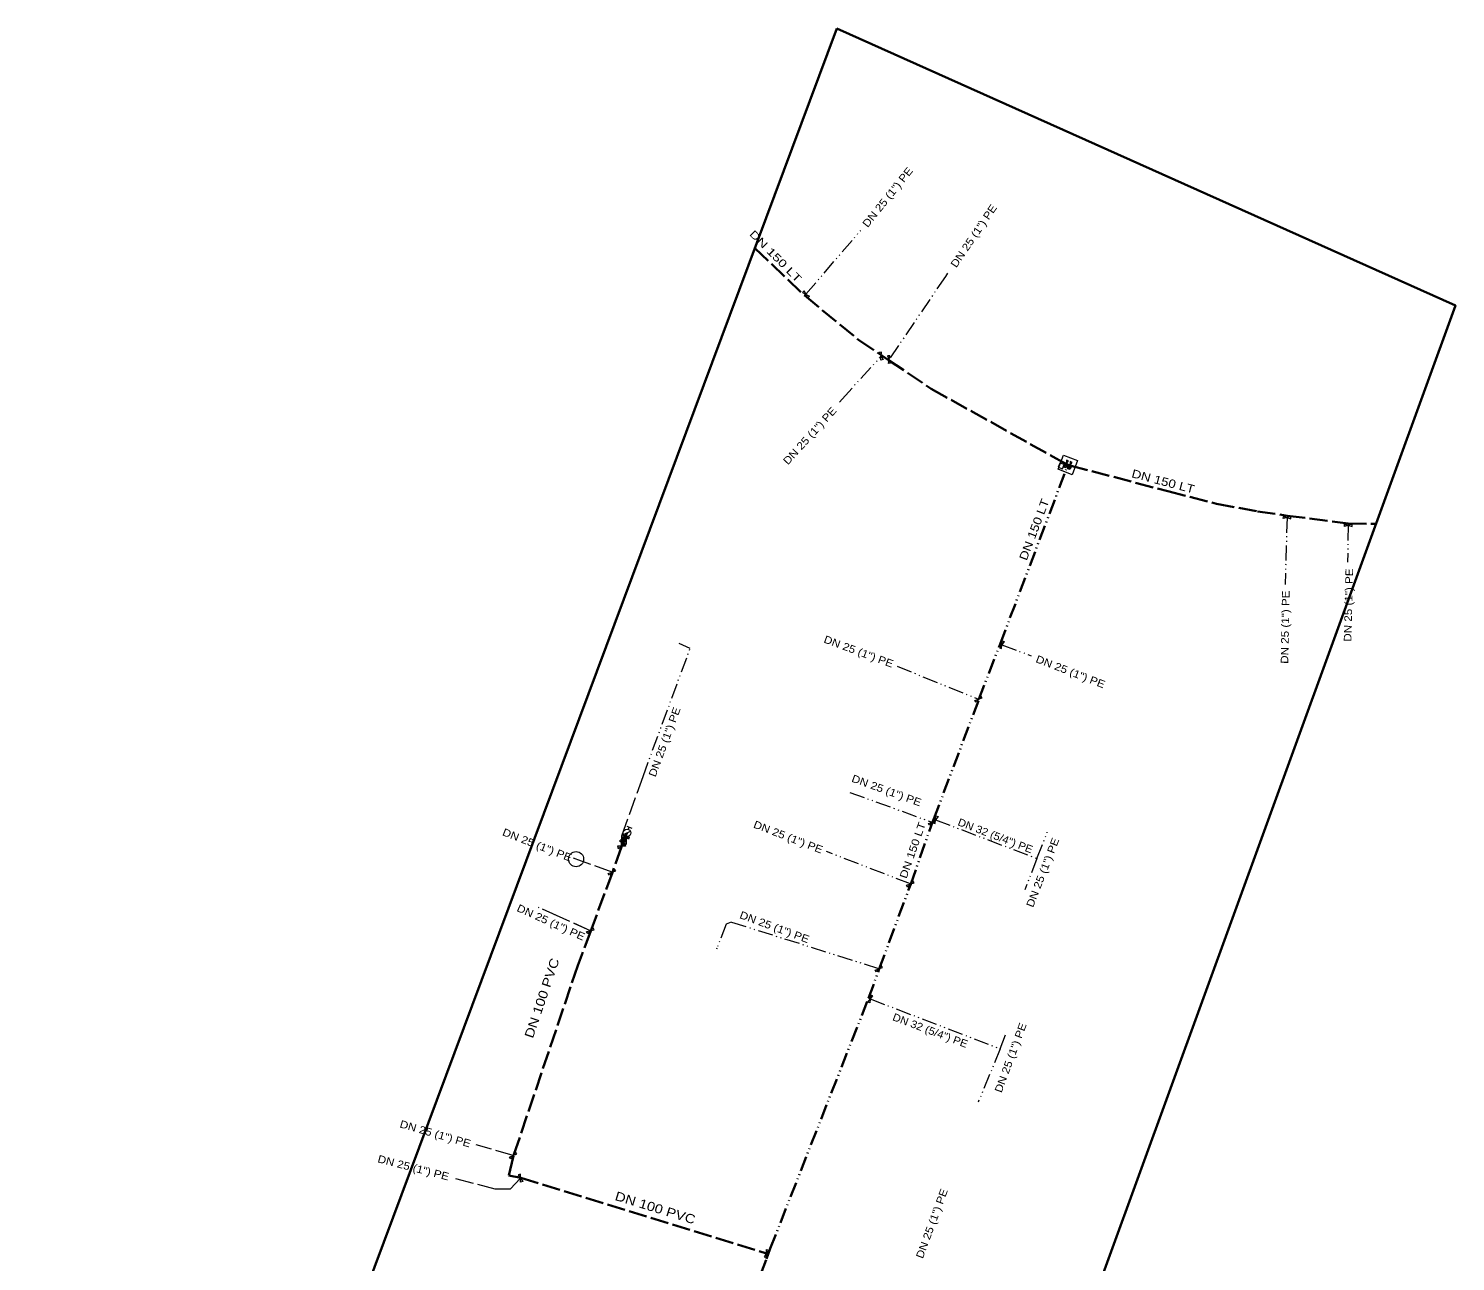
# Model space of a CAD drawing. Extents: x -644344 to -644155, y -1042441 to -1042139.
# Drawn here: x -644344 to -644155.2, y -1042301.7 to -1042138.6 of the extents above; entities that cross this region are included whole.
import ezdxf
from ezdxf.enums import TextEntityAlignment as Align

# ---------------------------------------------------------------- set-up
doc = ezdxf.new("R2010")
doc.units = 0
doc.header["$LTSCALE"] = 0.4
doc.linetypes.add('DASH_DOUBLE_DOT', pattern=[9.2, 5, -1.2, 0.3, -1.2, 0.3, -1.2])
doc.linetypes.add('LONG_DASHED', pattern=[7.5, 6, -1.5])
for name, color, linetype, lineweight in [('10', 7, 'Continuous', 13), ('13', 7, 'Continuous', 13), ('21', 7, 'LONG_DASHED', 35), ('22', 7, 'DASH_DOUBLE_DOT', 35), ('31', 7, 'LONG_DASHED', 13), ('32', 7, 'DASH_DOUBLE_DOT', 13), ('63', 7, 'Continuous', 35)]:
    doc.layers.add(name, color=color, linetype=linetype, lineweight=lineweight)
doc.layers.add('29', color=7, linetype='Continuous')
doc.layers.add('39', color=7, linetype='Continuous')

msp = doc.modelspace()

# ---------------------------------------------------------------- linework, layer by layer
at = {"layer": '10'}
for p, q in [((-644265.232, -1042245.181), (-644264.321, -1042244.77)), ((-644264.82, -1042244.103), (-644264.166, -1042244.35)), ((-644264.599, -1042244.507), (-644264.493, -1042244.227))]:
    msp.add_line(p, q, dxfattribs=at)
for points in [[(-644241.571, -1042173.495), (-644240.649, -1042173.985), (-644240.859, -1042174.198), (-644241.36, -1042173.282)], [(-644231.403, -1042181.467), (-644230.899, -1042182.38), (-644231.192, -1042182.444), (-644231.11, -1042181.403)], [(-644230.32, -1042181.901), (-644229.908, -1042182.861), (-644230.206, -1042182.895), (-644230.022, -1042181.867)], [(-644207.036, -1042195.028), (-644205.166, -1042195.738), (-644205.876, -1042197.608), (-644207.746, -1042196.898)], [(-644206.646, -1042195.667), (-644206.738, -1042196.707), (-644207.017, -1042196.596), (-644206.367, -1042195.778)], [(-644206.153, -1042195.866), (-644206.237, -1042196.907), (-644206.516, -1042196.798), (-644205.874, -1042195.975)], [(-644207.073, -1042196.536), (-644206.032, -1042196.61), (-644206.138, -1042196.89), (-644206.967, -1042196.256)], [(-644176.946, -1042203.144), (-644177.954, -1042203.416), (-644177.946, -1042203.116), (-644176.954, -1042203.444)], [(-644168.862, -1042204.145), (-644169.859, -1042204.454), (-644169.862, -1042204.154), (-644168.859, -1042204.445)], [(-644215.223, -1042220.614), (-644215.15, -1042219.572), (-644214.87, -1042219.678), (-644215.504, -1042220.508)], [(-644217.958, -1042226.882), (-644218.592, -1042227.71), (-644218.768, -1042227.467), (-644217.782, -1042227.125)], [(-644224.107, -1042243.15), (-644224.742, -1042243.979), (-644224.918, -1042243.736), (-644223.931, -1042243.393)], [(-644224.003, -1042243.75), (-644223.918, -1042242.71), (-644223.639, -1042242.819), (-644224.282, -1042243.641)], [(-644265.957, -1042247.028), (-644265.077, -1042246.466), (-644264.995, -1042246.755), (-644266.039, -1042246.739)], [(-644265.789, -1042246.061), (-644264.869, -1042246.454), (-644264.858, -1042245.154)], [(-644265.534, -1042245.459), (-644264.492, -1042245.537), (-644264.6, -1042245.817), (-644265.426, -1042245.179)], [(-644265.523, -1042246.012), (-644265.017, -1042246.227), (-644265.011, -1042245.513)], [(-644266.444, -1042249.768), (-644267.094, -1042250.584), (-644267.266, -1042250.338), (-644266.272, -1042250.014)], [(-644226.967, -1042251.329), (-644227.631, -1042252.135), (-644227.798, -1042251.886), (-644226.8, -1042251.578)], [(-644269.261, -1042257.531), (-644269.974, -1042258.294), (-644270.125, -1042258.035), (-644269.11, -1042257.791)], [(-644231.141, -1042262.524), (-644231.767, -1042263.36), (-644231.945, -1042263.118), (-644230.963, -1042262.766)], [(-644232.558, -1042266.42), (-644232.642, -1042267.461), (-644232.922, -1042267.351), (-644232.278, -1042266.529)], [(-644279.561, -1042287.215), (-644280.135, -1042288.087), (-644280.328, -1042287.858), (-644279.368, -1042287.444)], [(-644279.165, -1042290.221), (-644278.578, -1042291.085), (-644278.865, -1042291.176), (-644278.879, -1042290.132)], [(-644246.341, -1042301.125), (-644246.333, -1042300.081), (-644246.047, -1042300.169), (-644246.627, -1042301.037)]]:
    msp.add_lwpolyline(points, close=True, dxfattribs=at)
for centre, radius in [((-644264.7757, -1042244.9748), 0.5), ((-644271.524, -1042248.448), 0.9994)]:
    msp.add_circle(centre, radius, dxfattribs=at)
at = {"layer": '13'}
msp.add_lwpolyline([(-644207.513, -1042196.062), (-644207.728, -1042196.623), (-644207.167, -1042196.838), (-644206.952, -1042196.277)], close=True, dxfattribs=at)
at = {"layer": '21'}
for p, q in [((-644247.856, -1042167.649), (-644241.275, -1042173.927)), ((-644231.083, -1042181.849), (-644230.17, -1042182.464)), ((-644206.692, -1042196.187), (-644206.456, -1042196.318)), ((-644206.456, -1042196.318), (-644206.195, -1042196.387)), ((-644177.443, -1042203.031), (-644169.363, -1042204.05)), ((-644169.363, -1042204.05), (-644165.703, -1042204.126)), ((-644278.833, -1042290.612), (-644246.337, -1042300.603)), ((-644246.337, -1042300.603), (-644246.098, -1042300.677))]:
    msp.add_line(p, q, dxfattribs=at)
for points in [[(-644241.275, -1042173.927), (-644234.14, -1042179.79), (-644231.083, -1042181.849)], [(-644230.17, -1042182.464), (-644224.533, -1042186.26), (-644206.692, -1042196.187)], [(-644206.195, -1042196.387), (-644193.214, -1042199.796), (-644186.796, -1042201.444), (-644181.386, -1042202.459), (-644177.443, -1042203.031)], [(-644264.776, -1042244.975), (-644265.013, -1042245.498), (-644265.013, -1042245.498), (-644265.093, -1042245.706)], [(-644265.519, -1042246.819), (-644266.714, -1042250.196), (-644269.57, -1042257.934), (-644271.296, -1042262.513)], [(-644265.093, -1042245.706), (-644265.519, -1042246.819), (-644265.519, -1042246.819), (-644266.714, -1042250.196), (-644269.57, -1042257.934)], [(-644269.57, -1042257.934), (-644271.296, -1042262.513), (-644279.797, -1042287.666)], [(-644279.797, -1042287.666), (-644280.253, -1042289.551), (-644280.423, -1042290.303), (-644278.833, -1042290.612), (-644278.833, -1042290.612)]]:
    msp.add_lwpolyline(points, dxfattribs=at)
at = {"layer": '22'}
for p, q in [((-644215.418, -1042219.999), (-644206.552, -1042196.573)), ((-644206.552, -1042196.573), (-644206.456, -1042196.318)), ((-644218.228, -1042227.313), (-644215.418, -1042219.999)), ((-644224.194, -1042243.14), (-644218.228, -1042227.313)), ((-644224.38, -1042243.58), (-644224.194, -1042243.14)), ((-644227.252, -1042251.75), (-644224.38, -1042243.58))]:
    msp.add_line(p, q, dxfattribs=at)
for points in [[(-644231.407, -1042262.959), (-644227.252, -1042251.75), (-644227.252, -1042251.75)], [(-644232.832, -1042266.846), (-644231.407, -1042262.959), (-644231.407, -1042262.959)], [(-644246.098, -1042300.677), (-644245.835, -1042299.952), (-644232.832, -1042266.846)], [(-644247.1, -1042303.309), (-644246.322, -1042301.292), (-644246.098, -1042300.677), (-644246.098, -1042300.677)]]:
    msp.add_lwpolyline(points, dxfattribs=at)
at = {"layer": '31'}
for p, q in [((-644265.519, -1042246.819), (-644265.517, -1042246.747)), ((-644271.307, -1042248.527), (-644271.524, -1042248.448)), ((-644266.769, -1042250.176), (-644271.307, -1042248.527)), ((-644266.714, -1042250.196), (-644266.769, -1042250.176)), ((-644274.578, -1042255.685), (-644269.57, -1042257.934)), ((-644269.618, -1042257.913), (-644274.122, -1042255.89)), ((-644269.57, -1042257.934), (-644269.618, -1042257.913)), ((-644279.848, -1042287.651), (-644284.76, -1042286.232)), ((-644279.797, -1042287.666), (-644279.848, -1042287.651)), ((-644278.833, -1042290.612), (-644278.872, -1042290.653))]:
    msp.add_line(p, q, dxfattribs=at)
for points in [[(-644265.517, -1042246.747), (-644265.476, -1042245.366), (-644262.669, -1042237.506)], [(-644278.872, -1042290.653), (-644280.236, -1042292.118), (-644282.21, -1042292.092), (-644287.839, -1042290.635)]]:
    msp.add_lwpolyline(points, dxfattribs=at)
at = {"layer": '32'}
for p, q in [((-644241.11, -1042173.74), (-644233.868, -1042165.305)), ((-644222.652, -1042171.379), (-644230.114, -1042182.381)), ((-644222.372, -1042170.966), (-644222.652, -1042171.379)), ((-644241.275, -1042173.927), (-644241.11, -1042173.74)), ((-644230.114, -1042182.381), (-644230.17, -1042182.464)), ((-644236.671, -1042187.995), (-644236.334, -1042187.624)), ((-644229.038, -1042222.947), (-644218.275, -1042227.296)), ((-644235.308, -1042239.616), (-644224.425, -1042243.564)), ((-644224.194, -1042243.14), (-644223.96, -1042243.23)), ((-644224.425, -1042243.564), (-644224.38, -1042243.58)), ((-644223.96, -1042243.23), (-644210.546, -1042248.378)), ((-644210.546, -1042248.378), (-644209.182, -1042244.882)), ((-644271.524, -1042248.448), (-644271.852, -1042248.325)), ((-644227.299, -1042251.732), (-644238.407, -1042247.455)), ((-644210.546, -1042248.378), (-644212.136, -1042252.492)), ((-644274.122, -1042255.89), (-644276.867, -1042254.681)), ((-644232.832, -1042266.846), (-644232.6, -1042266.94)), ((-644232.6, -1042266.94), (-644215.4, -1042273.542)), ((-644215.4, -1042273.542), (-644214.604, -1042271.383)), ((-644215.4, -1042273.542), (-644218.329, -1042280.611))]:
    msp.add_line(p, q, dxfattribs=at)
for points in [[(-644236.334, -1042187.624), (-644231.151, -1042181.923), (-644231.083, -1042181.849)], [(-644177.443, -1042203.031), (-644177.45, -1042203.28), (-644177.722, -1042212.135)], [(-644169.363, -1042204.05), (-644169.36, -1042204.3), (-644169.443, -1042209.162)], [(-644262.669, -1042237.506), (-644256.431, -1042220.572), (-644257.899, -1042219.919)], [(-644215.418, -1042219.999), (-644215.187, -1042220.093), (-644211.305, -1042221.558)], [(-644218.275, -1042227.296), (-644218.228, -1042227.313), (-644218.228, -1042227.313)], [(-644227.252, -1042251.75), (-644227.299, -1042251.732), (-644227.299, -1042251.732)], [(-644231.454, -1042262.942), (-644251.002, -1042256.791), (-644251.658, -1042257.032), (-644252.92, -1042260.239), (-644252.962, -1042260.344)], [(-644231.407, -1042262.959), (-644231.454, -1042262.942), (-644231.454, -1042262.942)]]:
    msp.add_lwpolyline(points, dxfattribs=at)
at = {"layer": '63'}
msp.add_lwpolyline([(-644237.01, -1042138.605), (-644155.176, -1042175.215), (-644251.367, -1042439.381), (-644343.968, -1042425.024)], close=True, dxfattribs=at)

# ---------------------------------------------------------------- texts
at = {"layer": '29'}
for s, height, rotation, width, p in [('DN 150 LT', 1, 314.951, 1.4, (-644245.4821, -1042169.0722)), ('DN 150 LT', 1.1, 345.286, 1.2, (-644193.9847, -1042199.0172)), ('DN 150 LT', 1.1, 69.27, 1.2, (-644210.4024, -1042205.0557)), ('DN 150 LT', 1, 70.624, 1.2, (-644226.529, -1042247.4429)), ('DN 100 PVC', 1.2, 71.326, 1.2, (-644275.476, -1042267.0071)), ('DN 100 PVC', 1.2, 342.909, 1.2, (-644261.2143, -1042295.1269))]:
    msp.add_text(s, height=height, rotation=rotation, dxfattribs=dict(at, width=width)).set_placement(p, align=Align.CENTER)
at = {"layer": '39'}
for s, rotation, width, p in [('DN 25 (1") PE', 51.241, 1.15, (-644229.9158, -1042161.223)), ('DN 25 (1") PE', 55.855, 1.15, (-644218.5022, -1042166.3096)), ('DN 25 (1") PE', 47.723, 1.15, (-644240.2366, -1042192.7964)), ('DN 25 (1") PE', 88.582, 1.15, (-644168.8362, -1042214.8604)), ('DN 25 (1") PE', 88.89, 1.15, (-644177.2098, -1042217.7817)), ('DN 25 (1") PE', 339.62, 1.15, (-644234.3071, -1042221.4572)), ('DN 25 (1") PE', 338.84, 1.15, (-644206.2865, -1042224.1232)), ('DN 25 (1") PE', 69.778, 1.15, (-644259.3479, -1042233.1178)), ('DN 25 (1") PE', 340.059, 1.15, (-644230.6105, -1042239.8302)), ('DN 32 (5/4") PE', 339.004, 1.1, (-644216.2241, -1042245.8214)), ('DN 25 (1") PE', 338.709, 1.15, (-644276.8546, -1042247.0252)), ('DN 25 (1") PE', 338.942, 1.15, (-644243.6347, -1042245.9895)), ('DN 25 (1") PE', 68.869, 1.15, (-644209.3195, -1042250.3992)), ('DN 25 (1") PE', 335.811, 1.15, (-644275.0469, -1042257.2651)), ('DN 25 (1") PE', 339.743, 1.15, (-644245.4371, -1042257.9)), ('DN 32 (5/4") PE', 339.337, 1.1, (-644224.8424, -1042271.5773)), ('DN 25 (1") PE', 69.762, 1.15, (-644213.5668, -1042274.879)), ('DN 25 (1") PE', 343.887, 1.15, (-644290.2838, -1042285.2467)), ('DN 25 (1") PE', 345.488, 1.15, (-644293.1673, -1042289.7379)), ('DN 25 (1") PE', 69.838, 1.15, (-644223.9861, -1042296.8113))]:
    msp.add_text(s, height=1, rotation=rotation, dxfattribs=dict(at, width=width)).set_placement(p, align=Align.CENTER)

doc.saveas('drawing.dxf')
